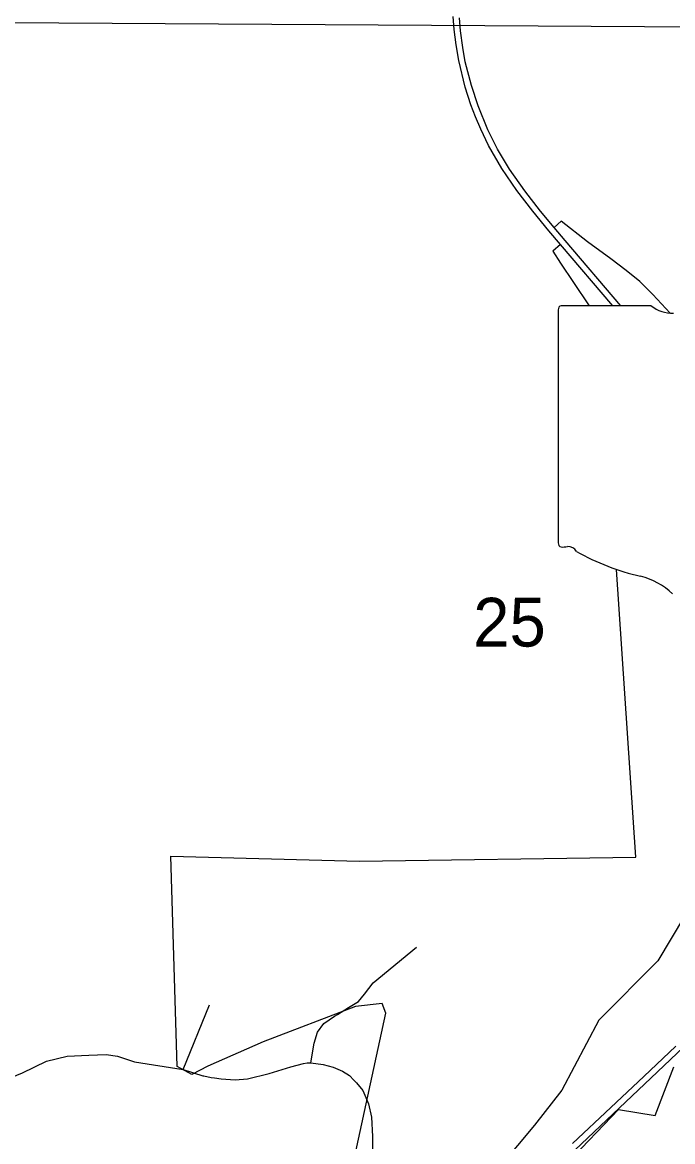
# Model space of a CAD drawing. Extents: x 2.1 to 8.9, y 14.1 to 20.9.
# Drawn here: x 7.48 to 8.038, y 19.144 to 20.105 of the extents above; entities that cross this region are included whole.
import ezdxf

# ---------------------------------------------------------------- set-up
doc = ezdxf.new("R2010")
doc.units = 0
for name, color, linetype in [('GM_X_County_Road', 7, 'Continuous'), ('GM_X_County_Road_Text', 7, 'Continuous'), ('GM_X_Interchange_Ramps', 7, 'Continuous'), ('GM_X_Rail_Line_Text', 7, 'Continuous'), ('GM_X_State_Shield', 7, 'Continuous'), ('GM_X_Township_Road', 7, 'Continuous'), ('GM_X_Unincorporated', 7, 'Continuous'), ('GM_X_Unincorporated_Text', 7, 'Continuous')]:
    doc.layers.add(name, color=color, linetype=linetype)

msp = doc.modelspace()

# ---------------------------------------------------------------- linework, layer by layer
at = {"layer": 'GM_X_County_Road'}
for p, q in [((7.93971, 19.85843), (7.93971, 19.65831)), ((8.01952, 19.86187), (7.9423, 19.86187))]:
    msp.add_line(p, q, dxfattribs=at)
for centre, radius, start, end in [((7.94273, 19.85885), 0.00305, 98.1301, 188.1301), ((8.03791, 19.8851), 0.02963, 231.61951, 271.11188), ((7.94276, 19.65787), 0.00308, 171.95839, 258.30661), ((7.94322, 19.67834), 0.02352, 267.33899, 280.60386), ((7.94804, 19.64676), 0.00848, 29.74838, 93.27175), ((8.0551, 19.82656), 0.20192, 240.41292, 257.1985), ((7.9949, 19.5684), 0.06318, 47.18416, 75.83597)]:
    msp.add_arc(centre, radius, start, end, dxfattribs=at)
at = {"layer": 'GM_X_Interchange_Ramps'}
msp.add_line((7.46528, 20.10504), (8.46027, 20.09858), dxfattribs=at)
at = {"layer": 'GM_X_Rail_Line_Text'}
for p, q in [((7.85047, 20.09891), (7.84943, 20.1101)), ((7.85588, 20.09789), (7.85484, 20.10908)), ((7.85197, 20.08588), (7.85047, 20.09891)), ((7.85769, 20.08357), (7.85588, 20.09789)), ((7.85446, 20.0723), (7.85197, 20.08588)), ((7.85987, 20.07127), (7.85769, 20.08357)), ((7.8599, 20.04961), (7.85446, 20.0723)), ((7.86514, 20.05088), (7.85987, 20.07127)), ((7.86477, 20.03441), (7.8599, 20.04961)), ((7.87083, 20.03339), (7.86514, 20.05088)), ((7.86861, 20.02402), (7.86477, 20.03441)), ((7.87924, 20.01275), (7.87083, 20.03339)), ((7.87318, 20.01334), (7.86861, 20.02402)), ((7.87993, 19.99932), (7.87318, 20.01334)), ((7.88758, 19.99614), (7.87924, 20.01275)), ((7.89129, 19.97968), (7.87993, 19.99932)), ((7.89793, 19.97918), (7.88758, 19.99614)), ((7.90419, 19.96078), (7.89129, 19.97968)), ((7.911, 19.96041), (7.89793, 19.97918)), ((7.91792, 19.94297), (7.90419, 19.96078)), ((7.92452, 19.94307), (7.911, 19.96041)), ((7.9317, 19.92614), (7.91792, 19.94297)), ((7.93628, 19.92895), (7.92452, 19.94307)), ((7.94168, 19.91447), (7.9317, 19.92614)), ((7.94565, 19.91791), (7.93628, 19.92895)), ((7.98644, 19.86187), (7.94168, 19.91447)), ((7.99334, 19.86187), (7.94565, 19.91791)), ((8.00836, 19.1887), (8.05266, 19.23059)), ((8.01306, 19.20043), (8.04052, 19.22627)), ((7.98492, 19.17381), (8.01306, 19.20043)), ((7.9432, 19.12716), (8.00836, 19.1887)), ((7.95203, 19.1428), (7.98492, 19.17381))]:
    msp.add_line(p, q, dxfattribs=at)
at = {"layer": 'GM_X_State_Shield'}
for p, q in [((7.78083, 19.28066), (7.81794, 19.31131)), ((7.77337, 19.27109), (7.78083, 19.28066)), ((7.76839, 19.26471), (7.77337, 19.27109)), ((7.75964, 19.25966), (7.76839, 19.26471)), ((7.73864, 19.24585), (7.74758, 19.25208)), ((7.74758, 19.25208), (7.75017, 19.2537)), ((7.75017, 19.2537), (7.75964, 19.25966)), ((7.73319, 19.23847), (7.73864, 19.24585)), ((7.73028, 19.22894), (7.73319, 19.23847)), ((7.72736, 19.21202), (7.73028, 19.22894)), ((7.47984, 19.20366), (7.50064, 19.21358)), ((7.50064, 19.21358), (7.51834, 19.21785)), ((7.51834, 19.21785), (7.53681, 19.21863)), ((7.53681, 19.21863), (7.55178, 19.21922)), ((7.55178, 19.21922), (7.5615, 19.21785)), ((7.5615, 19.21785), (7.57609, 19.21299)), ((7.57609, 19.21299), (7.61789, 19.20638)), ((7.72094, 19.21144), (7.72425, 19.21202)), ((7.72425, 19.21202), (7.72736, 19.21202)), ((7.72736, 19.21202), (7.73786, 19.21066)), ((7.46526, 19.19763), (7.47984, 19.20366)), ((7.61789, 19.20638), (7.63459, 19.20099)), ((7.67292, 19.19841), (7.69149, 19.20308)), ((7.69149, 19.20308), (7.71006, 19.20872)), ((7.71006, 19.20872), (7.72094, 19.21144)), ((7.73786, 19.21066), (7.74661, 19.20852)), ((7.74661, 19.20852), (7.75458, 19.20502)), ((7.75458, 19.20502), (7.76042, 19.20113)), ((7.63459, 19.20099), (7.63549, 19.20081)), ((7.63549, 19.20081), (7.64181, 19.19958)), ((7.64181, 19.19958), (7.64466, 19.19919)), ((7.64466, 19.19919), (7.65036, 19.19841)), ((7.65036, 19.19841), (7.66242, 19.19744)), ((7.66242, 19.19744), (7.67292, 19.19841)), ((7.76042, 19.20113), (7.7643, 19.19724)), ((7.7643, 19.19724), (7.76664, 19.19491)), ((7.76664, 19.19491), (7.77189, 19.1883)), ((7.77189, 19.1883), (7.77694, 19.17702)), ((7.77694, 19.17702), (7.77947, 19.16536)), ((7.77947, 19.16536), (7.78025, 19.14883)), ((7.78025, 19.14883), (7.78044, 19.12569))]:
    msp.add_line(p, q, dxfattribs=at)
at = {"layer": 'GM_X_Township_Road'}
for p, q in [((8.00622, 19.38873), (7.98974, 19.63551)), ((7.61267, 19.20906), (7.60727, 19.38935)), ((7.60727, 19.38935), (7.76922, 19.38533)), ((7.76922, 19.38533), (8.00622, 19.38873)), ((8.07464, 19.38285), (8.02502, 19.29976)), ((8.02502, 19.29976), (7.97441, 19.24867)), ((7.76576, 19.26035), (7.68632, 19.23008)), ((7.78871, 19.26305), (7.76576, 19.26035)), ((7.7916, 19.25476), (7.78871, 19.26305)), ((7.75651, 19.09318), (7.7916, 19.25476)), ((7.97441, 19.24867), (7.94289, 19.18858)), ((7.68632, 19.23008), (7.63909, 19.20926)), ((7.6252, 19.20212), (7.61267, 19.20906)), ((7.63909, 19.20926), (7.6252, 19.20212)), ((8.0228, 19.16687), (8.03891, 19.20857)), ((7.94289, 19.18858), (7.9193, 19.15858)), ((7.94699, 19.12564), (7.99145, 19.17211)), ((7.99145, 19.17211), (8.0228, 19.16687)), ((7.9193, 19.15858), (7.89001, 19.12359))]:
    msp.add_line(p, q, dxfattribs=at)
at = {"layer": 'GM_X_Unincorporated'}
for p, q in [((7.94211, 19.93448), (7.93628, 19.92895)), ((7.96479, 19.9167), (7.94211, 19.93448)), ((7.94168, 19.91447), (7.93493, 19.90862)), ((7.98481, 19.90203), (7.96479, 19.9167)), ((7.93493, 19.90862), (7.94163, 19.89854)), ((7.94163, 19.89854), (7.95289, 19.88172)), ((7.99788, 19.89223), (7.98481, 19.90203)), ((8.00956, 19.88273), (7.99788, 19.89223)), ((7.95289, 19.88172), (7.96634, 19.86187)), ((8.02124, 19.8712), (8.00956, 19.88273)), ((8.03571, 19.85556), (8.021, 19.87144))]:
    msp.add_line(p, q, dxfattribs=at)
at = {"layer": 'GM_X_Unincorporated_Text'}
msp.add_line((7.61789, 19.20638), (7.64044, 19.26196), dxfattribs=at)

# ---------------------------------------------------------------- texts
at = {"layer": 'GM_X_County_Road_Text'}
msp.add_text('25', height=0.041856, rotation=0.00001, dxfattribs=at).set_placement((7.86671, 19.56939))

doc.saveas('drawing.dxf')
